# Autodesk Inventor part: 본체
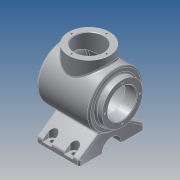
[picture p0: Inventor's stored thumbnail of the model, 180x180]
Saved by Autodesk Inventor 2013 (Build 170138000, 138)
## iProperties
Created: 2017-04
Part Number: 본체
Material: 알루미늄 6061
Document SubType Name: Modeling
Designer: Administrator
Mass: 1670.77 g
Surface Area: 1066.89 cm^2
Volume: 616.519 cm^3
Density: 2.71 g/cm^3
Author: Administrator
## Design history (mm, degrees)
sketch "스케치1"
  geometry: L1 (-48.168, 0)-(59.832, 0); L2 (-48.168, 0)-(-48.168, 50); L3 (-48.168, 50)-(48.168, 50); A1 r 113 centre (-53.168, 0) between (59.832, 0) and (48.168, 50); 5 further points
  constraints: 6 end point, 3 point on line, 2 coincident, 2 horizontal alignment, 2 midpoint, 2 perpendicular, 2 point on circle, 2 vertical alignment, 1 centre point, 1 horizontal
  dimensions: "d0" = 113 radius of A1; "d3" = 108 distance from line of L1.end L2; "d4" = 100 diameter of L3 L1
revolve "회전1" sketch "스케치1" stored, may be unused: angle "d5" = 90 deg
node "작업 평면1"
node "작업 평면2"
sketch "스케치5"
  geometry: C1 r 38 at (0, 0)
  constraints: 1 centre point
  dimensions: "d27" = 76 diameter of C1
extrude "돌출4" join sketch "스케치5" distance "d29" = 12; taper "d30" = 0 deg
node "작업 평면3"
sketch "스케치7"
  geometry: L1 (82, 60)-(82, -60); L2 (82, -60)-(72, -60); L3 (72, -60)-(45.101, -21.584); L4 (82, 60)-(72, 60); L5 (72, 60)-(45.101, 21.584); A1 r 50 centre (0, 0) between (45.101, 21.584) and (45.101, -21.584) reference; 2 further points
  constraints: 10 end point, 2 point on circle, 1 horizontal, 1 horizontal alignment, 1 midpoint, 1 parallel, 1 vertical
  dimensions: "d32" = 120 distance of L1.start L1.end; "d34" = 55 deg angle of L5 L4; "d36" = 55 deg angle of L3 L2; "d38" = 10 distance of L1.start L4.end; "d39" = 10 distance of L1.end L2.end; "d40" = 82 distance from line of L1 point (0, 0)
extrude "돌출5" join sketch "스케치7" distance "d41" = 80; taper "d42" = 0 deg
sketch "스케치8"
  geometry: L1 (-48.168, 50)-(48.168, 50) reference; L2 (-48.168, 50)-(48.168, 50) reference; L3 (-48.168, -50)-(48.168, -50) reference; L4 (-60.168, 38)-(-60.168, -38) reference; L5 (-48.168, 38)-(-60.168, 38) reference; L6 (-48.168, -38)-(-60.168, -38) reference; L7 (-38.168, 40)-(41.748, 40); L8 (-51.924, -40)-(41.748, -40); L9 (49.832, 0)-(-90.051, 0); L10 (-38.168, 40)-(-38.168, 0); A1 r 113 centre (-53.168, 0) between (48.168, -50) and (48.168, 50) reference; A2 r 103 centre (-53.168, 0) between (49.832, 0) and (41.748, 40); 2 further points
  constraints: 8 end point, 3 parallel, 3 point on circle, 2 point on line, 1 centre point, 1 perpendicular
  dimensions: "d45" = 10 radial gap between concentric circles of A2 A1; "d46" = 40 distance between parallel lines of L9 L7; "d47" = 40 distance between parallel lines of L8 L9; "d48" = 22 distance between parallel lines of L10 L4
revolve "회전2" sketch "스케치8" stored, may be unused: angle "d49" = 90 deg
sketch "스케치10"
  geometry: L1 (82, -60)-(82, 60) reference; C1 r 18 at (82, 0); A1 r 50 centre (0, 0) between (45.101, -21.584) and (45.101, 21.584) reference
  constraints: 1 centre point, 1 horizontal alignment, 1 midpoint
  dimensions: "d50" = 36 diameter of C1
extrude "돌출6" cut sketch "스케치10" distance "d52" = 80; taper "d53" = 0 deg
hole "구멍1" diameter "d56" = 54; stored, may be unused: countersink angle "d60" = 90 deg, drill point angle "d62" = 0 deg; dims "d54" = 10, "d55" = 10, "d57" = 6, "d58" = 4, "d59" = 2, "d61" = 22
node "작업 평면4"
sketch "스케치11"
  geometry: L1 (48.168, 50)-(48.168, -50) reference; C1 r 38 at (-1.832, 0); 1 further point
  constraints: 1 centre point, 1 horizontal alignment
  dimensions: "d64" = 76 diameter of C1; "d66" = 50 distance from line of C1.centre L1
extrude "돌출7" join sketch "스케치11" stored distance "d67" = 80; taper "d68" = 0 deg
sketch "스케치13" dims "d71" = 65
  geometry: C1 r 27 at (0, 0) reference; 2 further points
  constraints: 2 vertical alignment, 1 coincident, 2 other
hole "구멍2" sketch "스케치13" at (0, 32.5) diameter "d73" = 3.242; stored, may be unused: countersink angle "d77" = 90 deg, drill point angle "d79" = 118 deg; dims "d74" = 8, "d75" = 4, "d76" = 2, "d78" = 10
sketch "스케치14" dims "d83" = 65
  geometry: C1 r 38 at (0, 0) reference; 3 further points
  constraints: 2 vertical alignment, 1 coincident, 2 other
hole "구멍3" sketch "스케치14" at (0, 32.5) diameter "d85" = 3.242; stored, may be unused: countersink angle "d89" = 90 deg, drill point angle "d91" = 118 deg; dims "d86" = 8, "d87" = 4, "d88" = 2, "d90" = 10
hole "구멍4" diameter "d97" = 54; stored, may be unused: countersink angle "d101" = 90 deg, drill point angle "d103" = 0 deg; dims "d95" = 10, "d96" = 10, "d98" = 8, "d99" = 4, "d100" = 2, "d102" = 59.75
fillet "모깎기1" dims "d104" = 3
chamfer "모따기1" distance "d105" = 1; stored, may be unused: second distance "d106" = 2, angle "d107" = 45 deg
fillet "모깎기2" dims "d108" = 3
fillet "모깎기3" dims "d109" = 3
fillet "모깎기4" dims "d110" = 3
fillet "모깎기5" dims "d111" = 3
fillet "모깎기6" dims "d112" = 3
node "작업 평면5"
sketch "스케치15"
  geometry: L1 (12, 32)-(12, 64.084); L2 (28, 32)-(28, 64.084); L3 (12, 64.084)-(28, 64.084); L4 (3, 42)-(77, 42) reference; L5 (0, 3.271)-(0, 39) reference; L6 (40, 42)-(40, 76.749); L7 (68, 32)-(68, 64.084); L8 (52, 32)-(52, 64.084); L9 (68, 64.084)-(52, 64.084); A1 r 8 centre (20, 32) between (12, 32) and (28, 32); A2 r 8 centre (60, 32) between (52, 32) and (68, 32); 1 further point
  constraints: 14 end point, 5 symmetric about line, 4 point on circle, 2 centre point, 2 parallel, 2 tangent, 1 midpoint, 1 perpendicular, 1 vertical, 1 other
  dimensions: "d114" = 16 distance between parallel lines of L2 L1; "d116" = 10 distance from line of A1.centre L4; "d117" = 20 distance from line of A1.centre L5
extrude "돌출8" cut sketch "스케치15" distance "d118" = 31.75; taper "d119" = 0 deg
extrude "돌출9" cut sketch "스케치15" distance "d120" = 32.5; taper "d121" = 0 deg
hole "구멍5" diameter "d124" = 8; stored, may be unused: countersink angle "d128" = 90 deg, drill point angle "d130" = 0 deg; dims "d122" = 10, "d123" = 10, "d125" = 8, "d126" = 4, "d127" = 2, "d129" = 59.75
hole "구멍6" diameter "d133" = 8; stored, may be unused: countersink angle "d137" = 90 deg, drill point angle "d139" = 0 deg; dims "d131" = 10, "d132" = 10, "d134" = 8, "d135" = 4, "d136" = 2, "d138" = 59.75
node "작업 평면6"
sketch "스케치17"
  geometry: 2 further points
  constraints: 1 coincident, 1 other
feature "엠보싱1" sketch "스케치17" dims "d141" = 0.5, "d142" = 0
node "솔리드1"
pattern_circular "원형 패턴1" dims angle "d81" = 360 deg
pattern_circular "원형 패턴2" dims angle "d93" = 360 deg
mirror "대칭1"
other parameters: "d6" = -82, "d22" = 65, "d31" = -8, "d63" = 65, "d113" = -6, "d140" = -106
